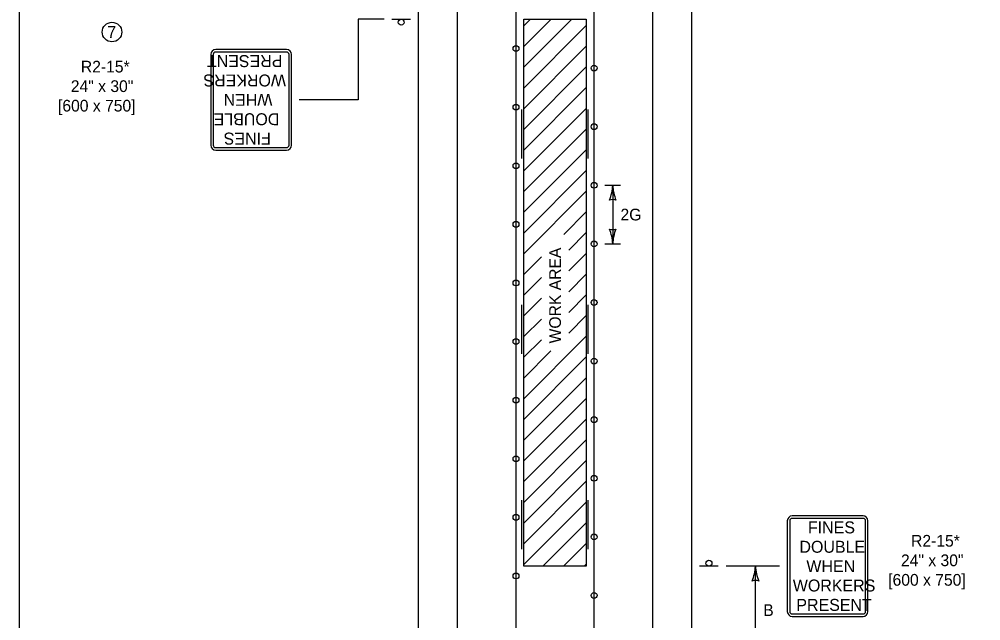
# Model space of a CAD drawing. Extents: x 49991.4 to 50021, y 49987.6 to 50011.4.
# Drawn here: x 50000.336 to 50005.26, y 50004.057 to 50007.137 of the extents above; entities that cross this region are included whole.
import ezdxf

# ---------------------------------------------------------------- set-up
doc = ezdxf.new("R2010")
doc.units = 0
for name, color, linetype in [('Level 1', 7, 'Continuous'), ('Level 2', 7, 'Continuous'), ('Level 3', 7, 'Continuous')]:
    doc.layers.add(name, color=color, linetype=linetype)

msp = doc.modelspace()

# ---------------------------------------------------------------- linework, layer by layer
at = {"layer": 'Level 1'}
for p, q in [((50002.3797, 50000.3857), (50002.3797, 50009.3344)), ((50002.5797, 50000.3857), (50002.5797, 50009.3344)), ((50002.8797, 50000.3857), (50002.8797, 50009.3344)), ((50003.2797, 50000.3857), (50003.2797, 50009.3344)), ((50003.5797, 50000.3857), (50003.5797, 50009.3344)), ((50003.7797, 50000.3857), (50003.7797, 50009.3344)), ((50002.2437, 50007.1368), (50002.3397, 50007.1368)), ((50002.9197, 50007.103), (50002.9535, 50007.1368)), ((50002.9197, 50006.997), (50003.0596, 50007.1368)), ((50002.9197, 50006.8909), (50003.1656, 50007.1368)), ((50002.9197, 50006.7848), (50003.2397, 50007.1048)), ((50001.7046, 50006.9814), (50001.3417, 50006.9814)), ((50002.9197, 50006.6788), (50003.2397, 50006.9988)), ((50001.3166, 50006.9563), (50001.3166, 50006.4921)), ((50001.329, 50006.9563), (50001.329, 50006.4921)), ((50001.7046, 50006.969), (50001.3417, 50006.969)), ((50001.7173, 50006.4921), (50001.7173, 50006.9563)), ((50001.7297, 50006.4921), (50001.7297, 50006.9563)), ((50002.9197, 50006.5727), (50003.2397, 50006.8927)), ((50002.9197, 50006.4666), (50003.2397, 50006.7866)), ((50002.9197, 50006.3606), (50003.2397, 50006.6806)), ((50002.9097, 50006.424), (50002.9097, 50006.674)), ((50003.2497, 50006.424), (50003.2497, 50006.674)), ((50002.9197, 50006.2545), (50003.2397, 50006.5745)), ((50001.3417, 50006.4795), (50001.7046, 50006.4795)), ((50001.3417, 50006.4671), (50001.7046, 50006.4671)), ((50002.9197, 50006.1484), (50003.2397, 50006.4684)), ((50002.9197, 50006.0424), (50003.2397, 50006.3624)), ((50002.9197, 50005.9363), (50003.2397, 50006.2563)), ((50003.1247, 50006.0353), (50003.2397, 50006.1502)), ((50003.1497, 50005.9542), (50003.2397, 50006.0442)), ((50002.9197, 50005.8302), (50003.0097, 50005.9202)), ((50003.1497, 50005.8481), (50003.2397, 50005.9381)), ((50002.9197, 50005.7242), (50003.0097, 50005.8142)), ((50003.1497, 50005.742), (50003.2397, 50005.832)), ((50002.9197, 50005.6181), (50003.0097, 50005.7081)), ((50003.1497, 50005.636), (50003.2397, 50005.726)), ((50002.9097, 50005.424), (50002.9097, 50005.674)), ((50003.2497, 50005.424), (50003.2497, 50005.674)), ((50002.9197, 50005.512), (50003.0097, 50005.602)), ((50003.1497, 50005.5299), (50003.2397, 50005.6199)), ((50002.9197, 50005.1938), (50003.2397, 50005.5138)), ((50002.9197, 50005.406), (50003.0097, 50005.496)), ((50002.9197, 50005.2999), (50003.0582, 50005.4384)), ((50002.9197, 50005.0878), (50003.2397, 50005.4078)), ((50002.9197, 50004.9817), (50003.2397, 50005.3017)), ((50002.9197, 50004.8756), (50003.2397, 50005.1956)), ((50002.9197, 50004.7696), (50003.2397, 50005.0896)), ((50002.9197, 50004.6635), (50003.2397, 50004.9835)), ((50002.9197, 50004.5574), (50003.2397, 50004.8774)), ((50002.9197, 50004.4514), (50003.2397, 50004.7714)), ((50002.9097, 50004.424), (50002.9097, 50004.674)), ((50002.9197, 50004.3453), (50003.2397, 50004.6653)), ((50003.2497, 50004.424), (50003.2497, 50004.674)), ((50004.269, 50004.5689), (50004.269, 50004.1047)), ((50004.2814, 50004.5689), (50004.2814, 50004.1047)), ((50004.657, 50004.594), (50004.294, 50004.594)), ((50004.657, 50004.5816), (50004.294, 50004.5816)), ((50004.6696, 50004.1047), (50004.6696, 50004.5689)), ((50004.682, 50004.1047), (50004.682, 50004.5689)), ((50003.0173, 50004.3368), (50003.2397, 50004.5592)), ((50003.1234, 50004.3368), (50003.2397, 50004.4532)), ((50003.2294, 50004.3368), (50003.2397, 50004.3471)), ((50003.9157, 50004.3368), (50003.8197, 50004.3368)), ((50004.294, 50004.0921), (50004.657, 50004.0921)), ((50004.294, 50004.0797), (50004.657, 50004.0797))]:
    msp.add_line(p, q, dxfattribs=at)
for points in [[(50008.6146, 50011.2628), (50000.3356, 50011.2628), (50000.3356, 50000.0624), (50008.6146, 50000.0624)], [(50003.2397, 50007.1368), (50003.2397, 50004.3368), (50002.9197, 50004.3368), (50002.9197, 50007.1368)]]:
    msp.add_lwpolyline(points, close=True, dxfattribs=at)
for centre, radius in [((50002.2917, 50007.1217), 0.0152), ((50002.8797, 50006.9868), 0.015), ((50003.2797, 50006.8868), 0.015), ((50002.8797, 50006.6868), 0.015), ((50003.2797, 50006.5868), 0.015), ((50002.8797, 50006.3868), 0.015), ((50003.2797, 50006.2868), 0.015), ((50002.8797, 50006.0868), 0.015), ((50003.2797, 50005.9868), 0.015), ((50002.8797, 50005.7868), 0.015), ((50003.2797, 50005.6868), 0.015), ((50002.8797, 50005.4868), 0.015), ((50003.2797, 50005.3868), 0.015), ((50002.8797, 50005.1868), 0.015), ((50003.2797, 50005.0868), 0.015), ((50002.8797, 50004.8868), 0.015), ((50002.8797, 50004.8868), 0.015), ((50003.2797, 50004.7868), 0.015), ((50002.8797, 50004.5868), 0.015), ((50003.2797, 50004.4868), 0.015), ((50003.8676, 50004.352), 0.0152), ((50002.8797, 50004.2868), 0.015), ((50002.8797, 50004.2868), 0.015), ((50003.2797, 50004.1868), 0.015), ((50003.2797, 50004.1868), 0.015)]:
    msp.add_circle(centre, radius, dxfattribs=at)
for centre, radius, start, end in [((50001.3416, 50006.9563), 0.0251, 90, 180), ((50001.7045, 50006.9563), 0.0251, 360, 90), ((50001.3416, 50006.9563), 0.0127, 90, 180), ((50001.7045, 50006.9563), 0.0127, 360, 90), ((50001.3416, 50006.4921), 0.0251, 180, 270), ((50001.3416, 50006.4921), 0.0127, 180, 270), ((50001.7045, 50006.4921), 0.0127, 270, 360), ((50001.7045, 50006.4921), 0.0251, 270, 360), ((50004.2941, 50004.5689), 0.0251, 90, 180), ((50004.2941, 50004.5689), 0.0127, 90, 180), ((50004.657, 50004.5689), 0.0251, 0, 90), ((50004.657, 50004.5689), 0.0127, 0, 90), ((50004.2941, 50004.1047), 0.0251, 180, 270), ((50004.2941, 50004.1047), 0.0127, 180, 270), ((50004.657, 50004.1047), 0.0127, 270, 0), ((50004.657, 50004.1047), 0.0251, 270, 0)]:
    msp.add_arc(centre, radius, start, end, dxfattribs=at)
at = {"layer": 'Level 2'}
msp.add_circle((50000.8106, 50007.0714), 0.0501, dxfattribs=at)
at = {"layer": 'Level 3'}
for p, q in [((50002.2037, 50007.1368), (50002.0718, 50007.1368)), ((50003.3347, 50006.2868), (50003.4147, 50006.2868)), ((50003.3747, 50006.2868), (50003.3747, 50005.9868)), ((50003.3347, 50005.9868), (50003.4147, 50005.9868)), ((50004.2074, 50004.3368), (50003.9557, 50004.3368)), ((50004.1057, 50003.8868), (50004.1057, 50004.3368)), ((50004.229, 50004.3368), (50004.2074, 50004.3368))]:
    msp.add_line(p, q, dxfattribs=at)
msp.add_lwpolyline([(50002.0718, 50007.1368), (50002.0718, 50006.7242), (50001.7697, 50006.7242)], dxfattribs=at)
for centre, radius, start, end in [((50003.1526, 50006.296), 0.2223, 337.456, 357.6395), ((50003.6074, 50006.2983), 0.233, 182.8273, 202.0772), ((50003.3747, 50006.1586), 0.0548, 72.1388, 107.8612), ((50003.3747, 50006.1151), 0.0548, 252.1388, 287.8612), ((50003.142, 50005.9753), 0.233, 2.8273, 22.0772), ((50003.5968, 50005.9777), 0.2223, 157.456, 177.6395), ((50003.8836, 50004.346), 0.2223, 337.456, 357.6395), ((50004.3384, 50004.3483), 0.233, 182.8273, 202.0772), ((50004.1057, 50004.2086), 0.0548, 72.1388, 107.8612)]:
    msp.add_arc(centre, radius, start, end, dxfattribs=at)

# ---------------------------------------------------------------- texts
at = {"layer": 'Level 1'}
for s, p in [('PRESENT', (50001.6835, 50006.9531)), ('WORKERS', (50001.7016, 50006.8539)), ('WHEN', (50001.6321, 50006.7547)), ('DOUBLE', (50001.6676, 50006.6556)), ('FINES', (50001.6241, 50006.5564))]:
    msp.add_text(s, height=0.06119, rotation=180, dxfattribs=at).set_placement(p)
for s, p in [('FINES', (50004.3745, 50004.5047)), ('DOUBLE', (50004.331, 50004.4055)), ('WHEN', (50004.3665, 50004.3063)), ('WORKERS', (50004.2971, 50004.2072)), ('PRESENT', (50004.3152, 50004.108))]:
    msp.add_text(s, height=0.06119, dxfattribs=at).set_placement(p)
at = {"layer": 'Level 2'}
for s, p in [('7', (50000.7868, 50007.0414)), ('R2-15*', (50000.6513, 50006.8642)), ('24" x 30"', (50000.5998, 50006.7642)), ('[600 x 750]', (50000.5342, 50006.6642)), ('2G', (50003.4147, 50006.1068)), ('R2-15*', (50004.9027, 50004.4368)), ('24" x 30"', (50004.8511, 50004.3368)), ('[600 x 750]', (50004.7856, 50004.2368)), ('B', (50004.1457, 50004.0818))]:
    msp.add_text(s, height=0.06, dxfattribs=at).set_placement(p)
msp.add_text('WORK AREA', height=0.06, rotation=90, dxfattribs=at).set_placement((50003.1097, 50005.4772))

doc.saveas('drawing.dxf')
